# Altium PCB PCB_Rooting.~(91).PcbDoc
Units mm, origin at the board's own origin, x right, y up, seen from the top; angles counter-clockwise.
Board outline 68.5 x 51 mm, 4 copper layers (Top Layer, Mid-Layer 1, Mid-Layer 2, Bottom Layer); 59 components, 42 nets, 197 pads, 55 vias.
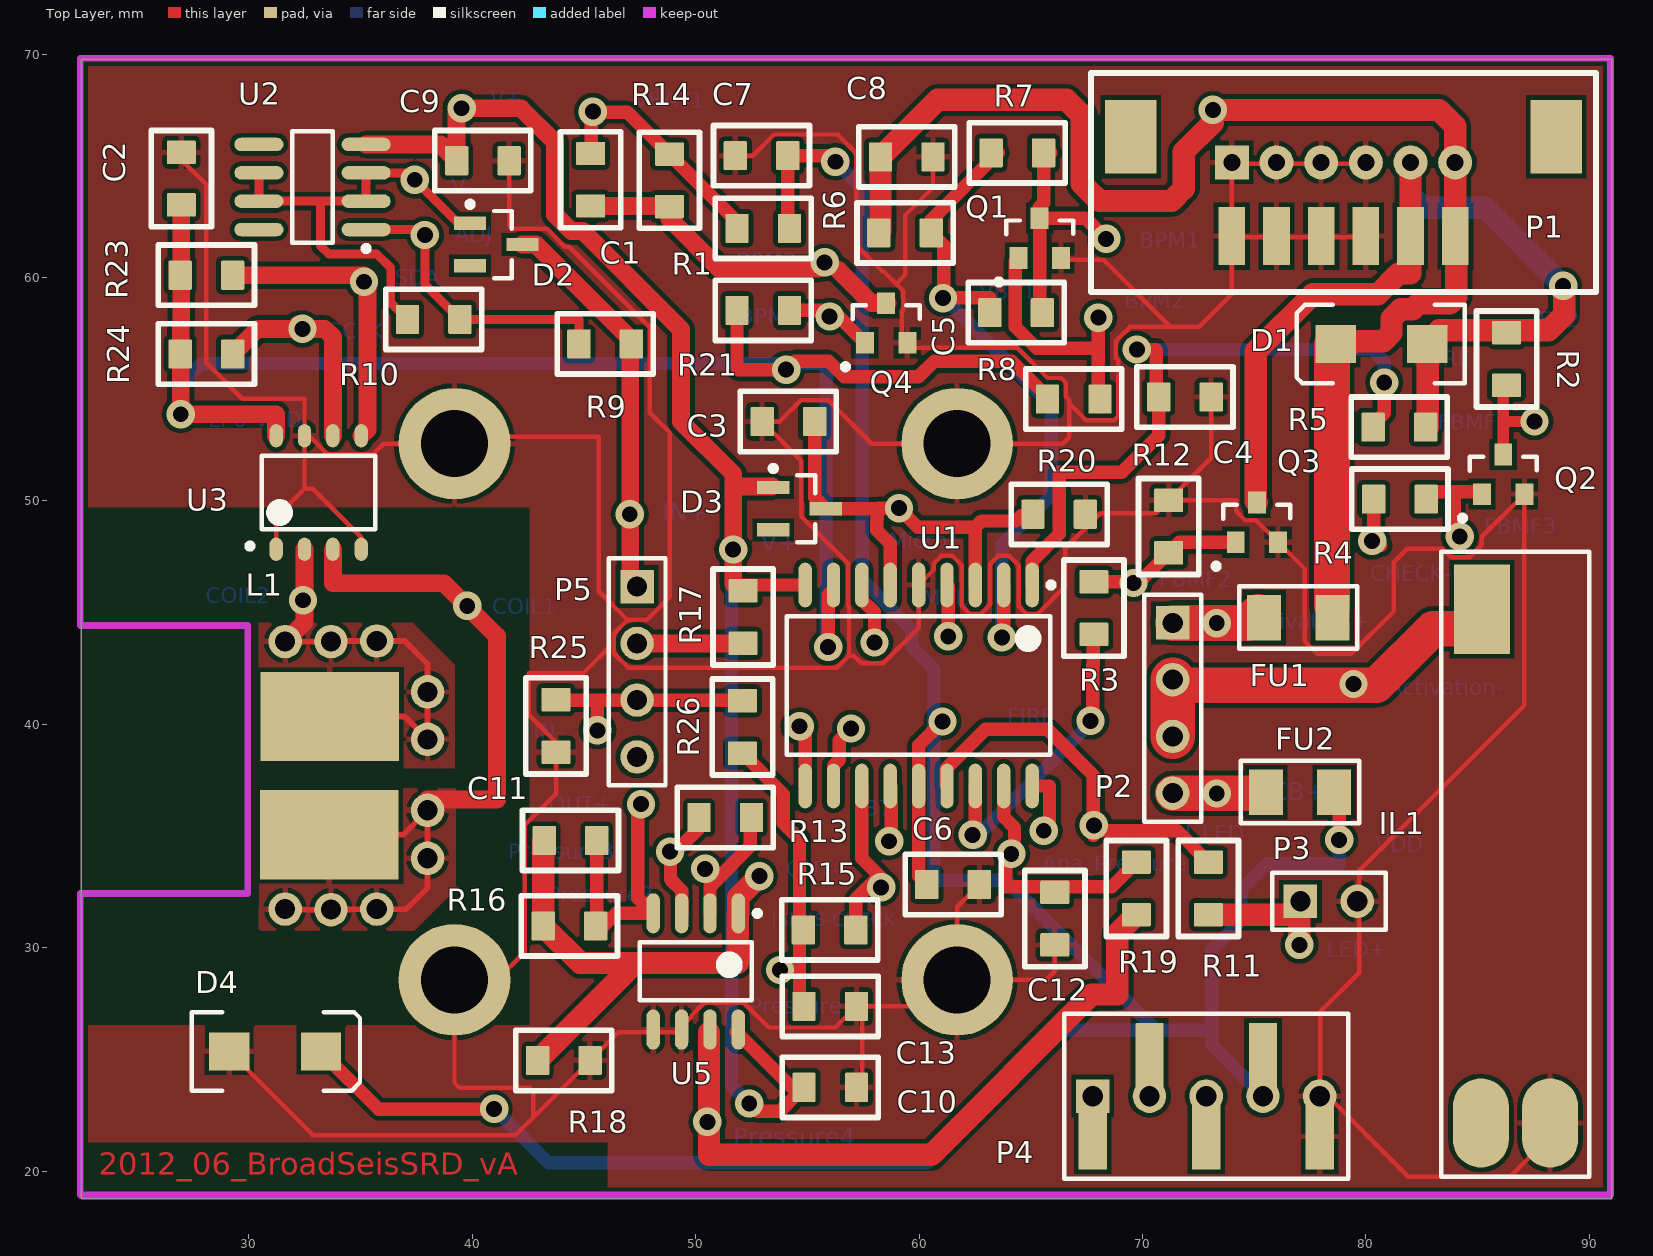
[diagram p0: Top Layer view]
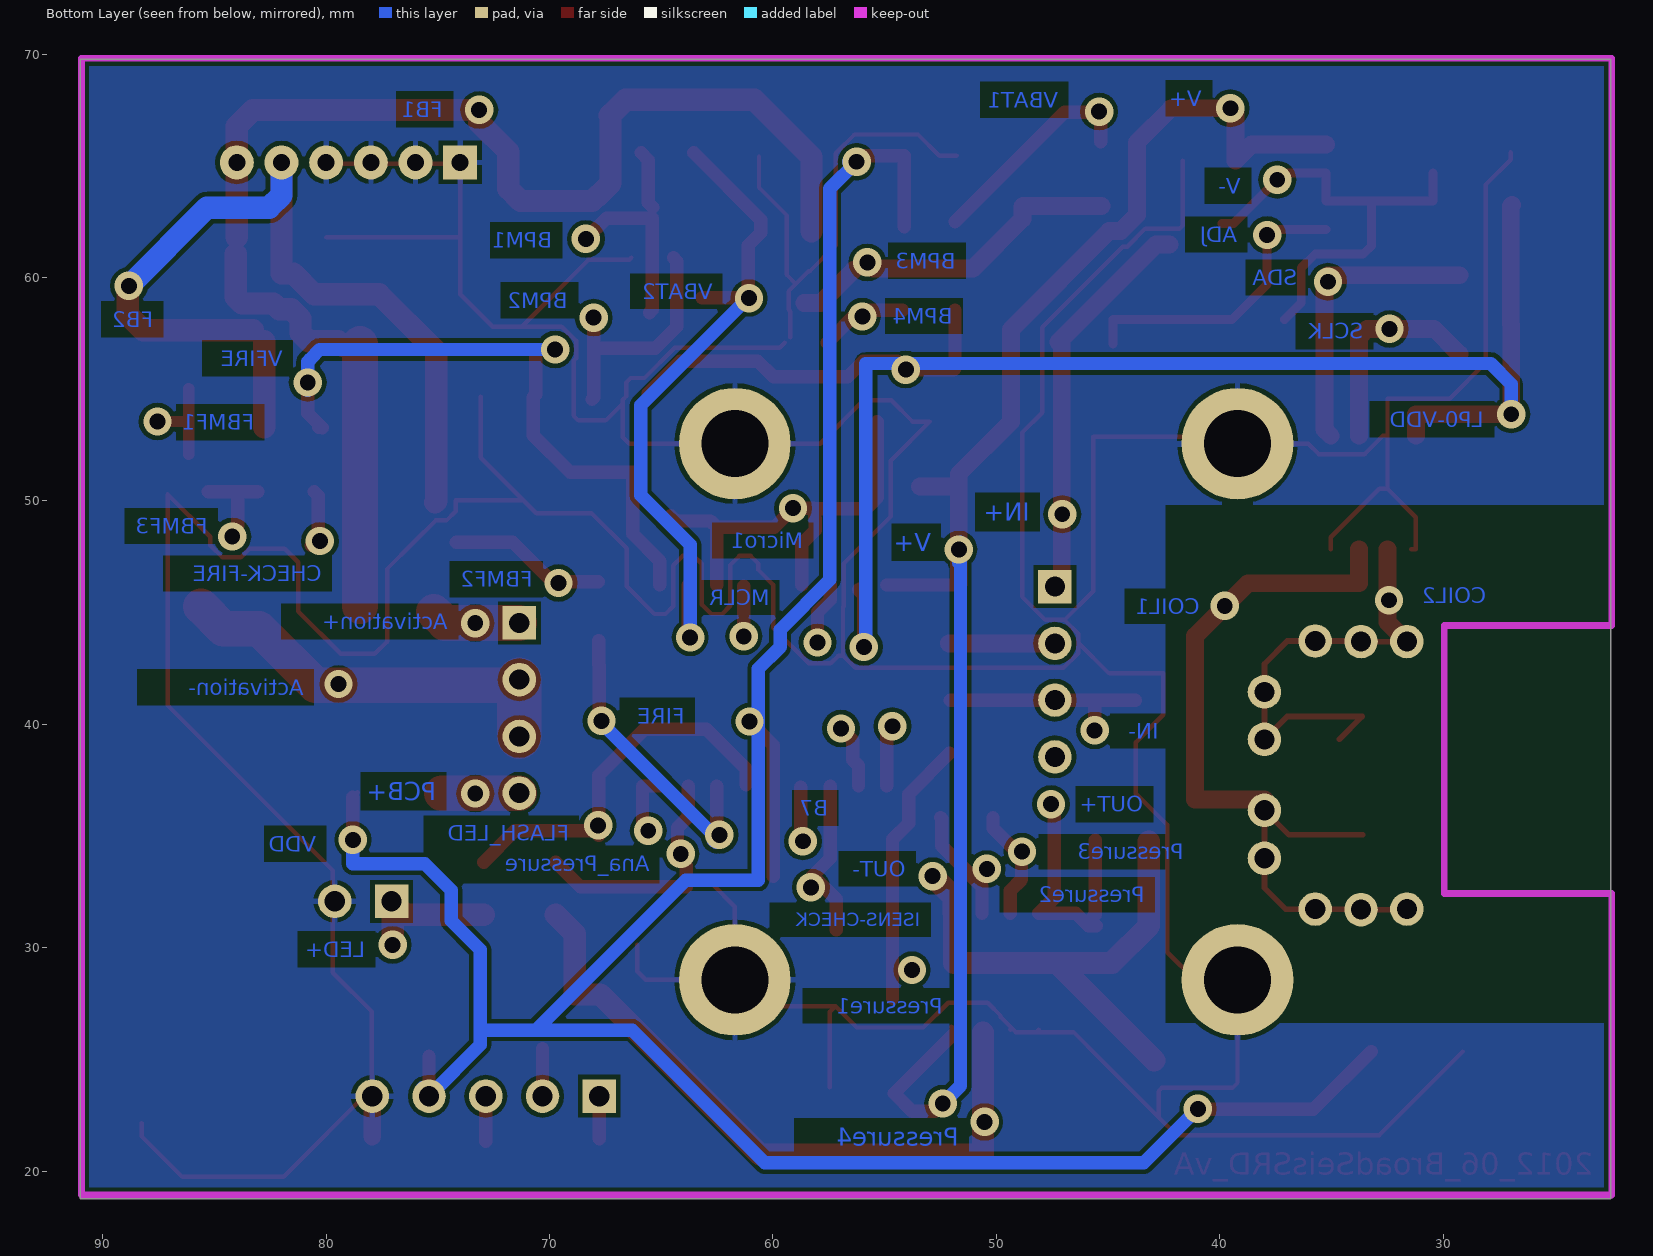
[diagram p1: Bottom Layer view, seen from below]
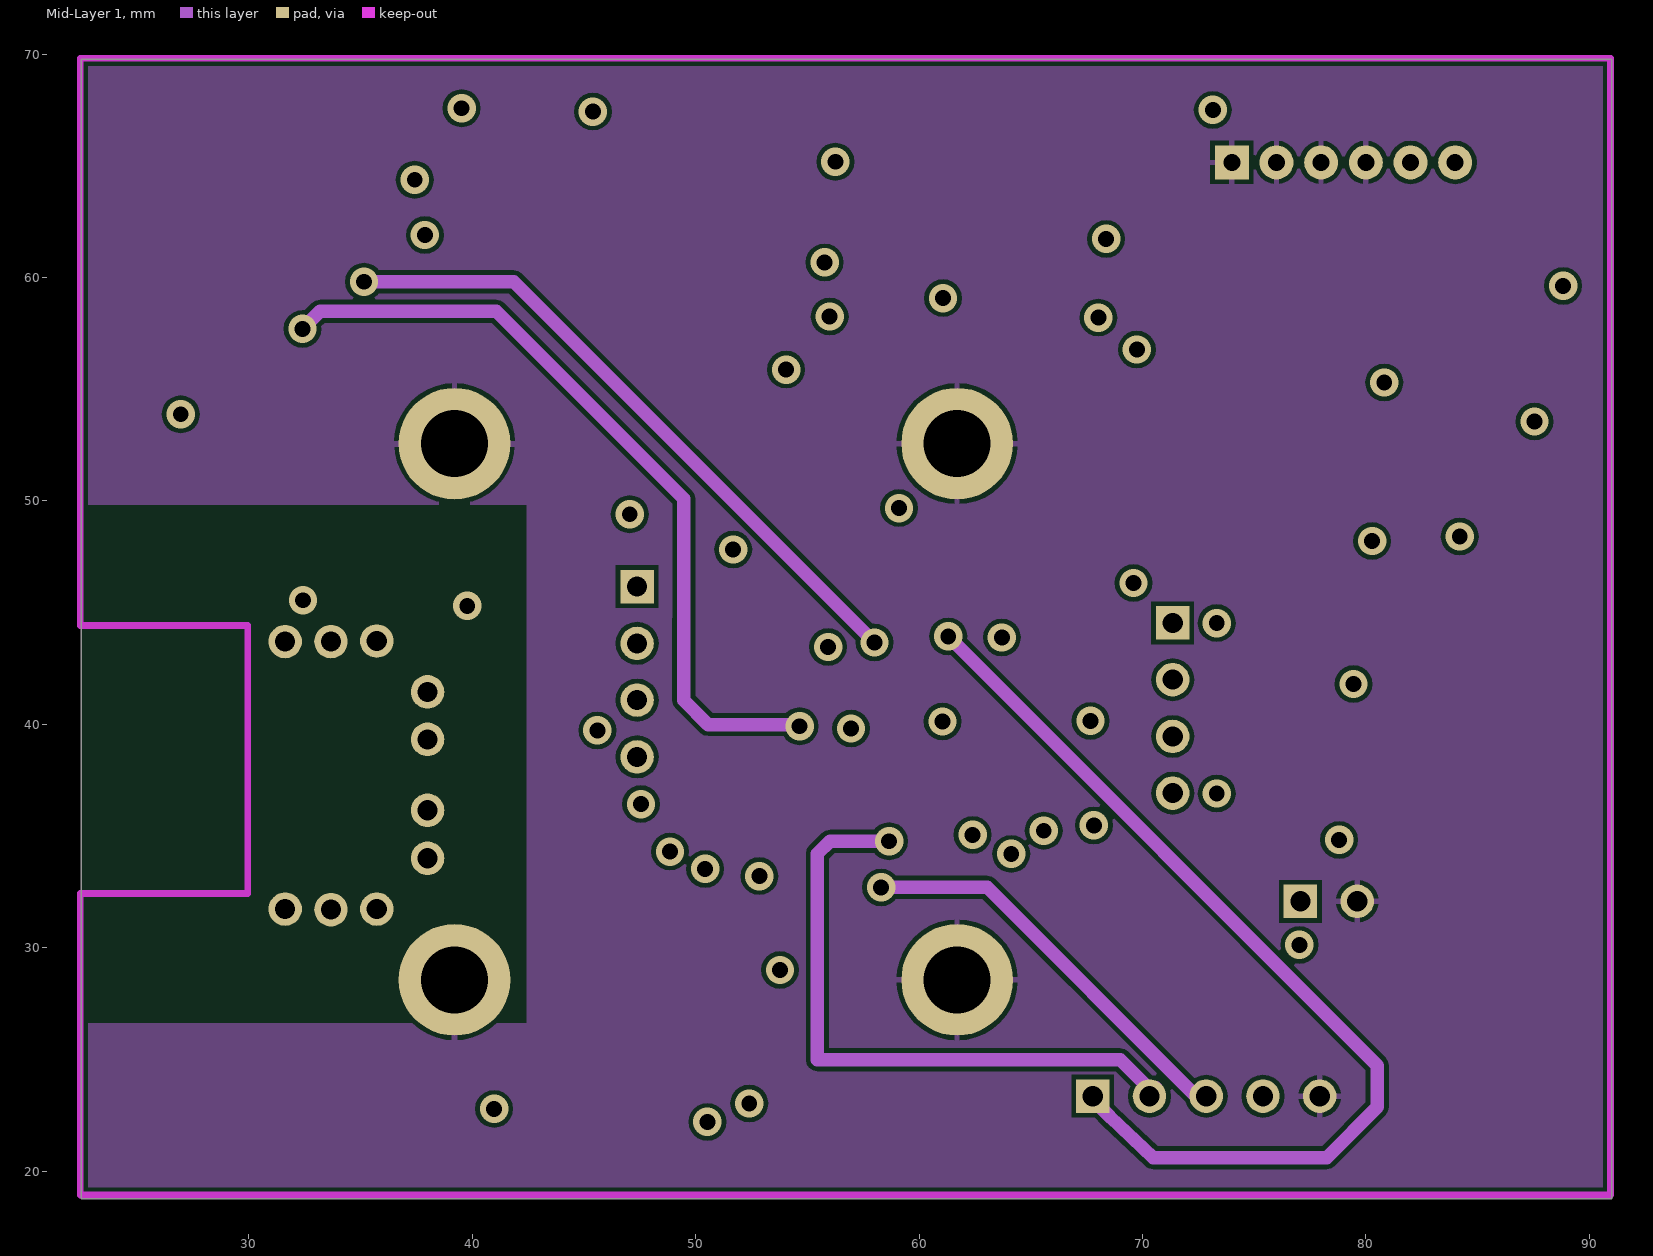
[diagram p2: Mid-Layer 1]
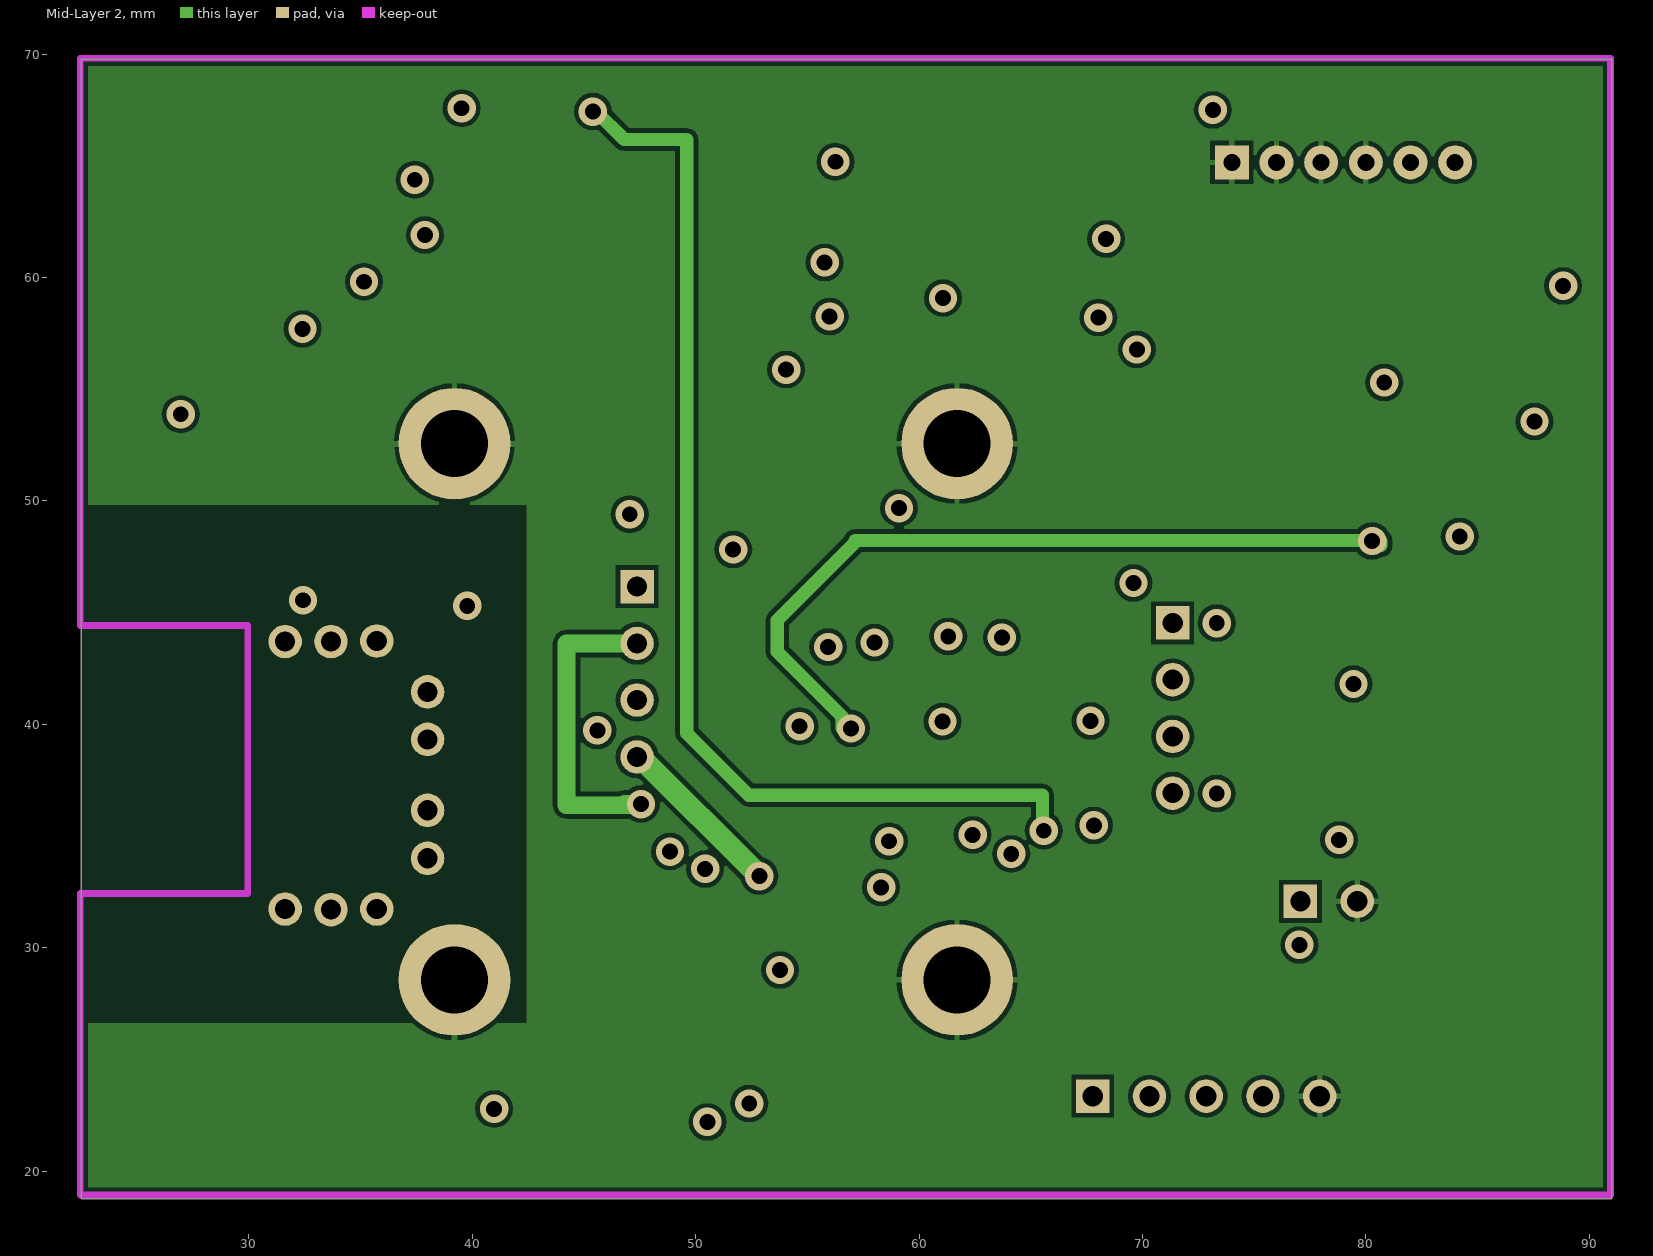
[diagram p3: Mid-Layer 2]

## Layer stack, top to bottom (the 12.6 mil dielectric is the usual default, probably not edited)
Top Layer: signal copper 0.0356
Dielectric: dielectric 0.32, FR-4, Dk 4.8
Mid-Layer 1: signal copper 0.0356
Dielectric: dielectric 0.32, FR-4, Dk 4.8
Mid-Layer 2: signal copper 0.0356
Dielectric: dielectric 0.32, FR-4, Dk 4.8
Bottom Layer: signal copper 0.0356

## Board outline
22.505,18.76 91.005,18.76 91.005,69.76 22.505,69.76

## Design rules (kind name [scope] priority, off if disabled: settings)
Clearance [All] p1: gap=0.2
HoleSize [All] p1: absolutevalues=TRUE maxlimit=5 minlimit=0.025 maxpercent=80.000 minpercent=20.000
PolygonConnect [All] p1: connectstyle=Relief reliefconductorwidth=0.254 reliefentries=4 polygonreliefangle="90 Angle"
RoomDefinition PCB_Schematics [InComponentClass('PCB_Schematics')] p1: confinementstyle=ConfineIn formatcopy=TRUE lockcomponents=FALSE outline 0,0 106.55,0 106.55,84.8 0,84.8
RoutingVias [All] p1: holewidth=0.6 width=1 viastyle="Through Hole" minholewidth=0.711 minwidth=1.27 maxholewidth=0.711 maxwidth=1.27
SilkscreenOverComponentPads [All] p1: minsilkscreentomaskgap=0.254
SolderMaskExpansion [All] p1: expansion=0.102
Width [All] p1: maxlimit=2 minlimit=0.2 preferedwidth=0.6
26 further rules are at their usual default settings.

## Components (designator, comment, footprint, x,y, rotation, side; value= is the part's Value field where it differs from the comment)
C1 "" 1608[0603] 45.3,64.375 r90 top
C2 "" 1608[0603] 26.975,64.425 r270 top
C3 "" 1608[0603] 54.15,53.55 r0 top
C4 "" 1608[0603] 71.9,54.65 r180 top
C5 "" 1608[0603] 64.35,58.425 r180 top
C6 "" 1608[0603] 61.525,32.825 r180 top
C7 "" 1608[0603] 52.95,65.45 r0 top
C8 "" 1608[0603] 59.45,65.4 r180 top
C9 "" 1608[0603] 40.475,65.225 r180 top
C10 "" 1608[0603] 56.025,23.75 r180 top
C11 "" 1608[0603] 44.4,34.8 r0 top
C12 "" 1608[0603] 66.075,31.3 r90 top
C13 "" 1608[0603] 56.025,27.375 r180 top
D1 "" DiodeRS1D(recommendedfootprint) 80.7,57.025 r180 top
D2 "" SOT-23_M 41.075,61.475 r0 top
D3 "" SOT-23_M 54.65,49.65 r0 top
D4 "" DiodeRS1D(recommendedfootprint) 31.175,25.35 r0 top
FU1 "1A" FU(recommendedfootprint) 76.975,44.775 r0 top
FU2 "200mA" FU(recommendedfootprint) 77.055,36.96 r180 top
IL1 "ILS" ILS 88.15,45.15 r270 top
L1 "" INDC4532 33.625,37.7 r270 top
P1 "ConnectorToFB" "HIROSE DF3DZ 6P-2V" 79,63.15 r0 top
P2 "Battery Pack pigtail" HDR1X4 71.355,44.535 r270 top
P3 "Connector to LED" HDR1X2 77.075,32.075 r0 top
P4 "Connector to Prog." HDR1X5 67.775,23.35 r0 top
P5 "Pressure Transducer pigtail" HDR1X4 47.38,46.16 r270 top
Q1 "" transistor_SOT-23(recommendedfootprint) 65.4,61.85 r90 top
Q2 "" transistor_SOT-23(recommendedfootprint) 86.15,51.275 r90 top
Q3 "" transistor_SOT-23(recommendedfootprint) 75.125,49.125 r90 top
Q4 "" transistor_SOT-23(recommendedfootprint) 58.525,58.05 r90 top
R1 "" J1-0603 53.025,62.2 r0 top
R2 "" J1-0603 86.3,56.35 r90 top
R3 "" J1-0603 67.825,45.2 r90 top
R4 "" J1-0603 81.525,50.075 r0 top
R5 "" J1-0603 81.5,53.3 r0 top
R6 "" J1-0603 59.375,62 r180 top
R7 "" J1-0603 64.4,65.575 r180 top
R8 "" J1-0603 66.925,54.55 r0 top
R9 "" J1-0603 45.95,57.025 r0 top
R10 "" J1-0603 38.275,58.125 r180 top
R11 "" J1-0603 72.95,32.65 r90 top
R12 "" J1-0603 71.175,48.85 r270 top
R13 "" J1-0603 51.325,35.825 r0 top
R14 "" J1-0603 48.825,64.35 r90 top
R15 "" J1-0603 56,30.8 r180 top
R16 "" J1-0603 44.35,30.975 r0 top
R17 "" J1-0603 52.125,44.8 r90 top
R18 "" 1608[0603] 44.1,24.95 r180 top
R19 "" J1-0603 69.725,32.65 r90 top
R20 "" J1-0603 66.275,49.4 r180 top
R21 "" J1-0603 53.025,58.525 r0 top
R23 "" J1-0603 28.1,60.1 r0 top
R24 "" J1-0603 28.1,56.575 r180 top
R25 "" J1-0603 43.75,39.925 r90 top
R26 "" J1-0603 52.1,39.875 r90 top
U1 "PIC16LF1827-I/SO" SOIC-SO18_L 59.98,41.735 r270 top
U2 "LM334D" SO8_N 32.85,64.05 r180 top
U3 "M24LR64" SO8N_N 33.125,50.375 r90 top
U5 "AD620BR" R-8D_N 50.005,28.935 r270 top

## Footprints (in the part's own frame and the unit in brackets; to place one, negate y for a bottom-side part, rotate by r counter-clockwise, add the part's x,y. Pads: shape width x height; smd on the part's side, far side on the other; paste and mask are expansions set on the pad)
1608[0603] [mm] "Chip Capacitor, Body 1.6x0.8mm, IPC High Density"
  rrect10% 1.05x1.3 smd: 1(-1.175,0) 2(1.175,0)
  silkscreen extent -2.15,-1.35 2.15,1.35
DiodeRS1D(recommendedfootprint) [mm] "DO-214-AB/SMC; 2 C-Bend Leads; Body 7.9 x 5.9 mm, inc. leads (LxW)"
  rect 1.8x1.7 smd: 1(-2.05,0) 2(2.05,0)
  silkscreen extent -3.73,-1.75 3.8,1.75
FU(recommendedfootprint) [mm] "Thru-Hole; 2 Leads"
  rect 1.52x2.03 smd: 1(-1.525,0) 2(1.525,0)
  silkscreen extent -2.65,-1.4 2.65,1.4
HDR1X2 [mm] "Connector; Header; 2 Position"
  rect 1.5x1.5 hole 0.9: 1(0,0)
  round 1.5 hole 0.9: 2(2.54,0)
  silkscreen extent -1.27,-1.27 3.81,1.27
HDR1X4 [mm] "Connector; Header; 4 Position"
  rect 1.5x1.5 hole 0.9: 1(0,0)
  round 1.5 hole 0.9: 2(2.54,0) 3(5.08,0) 4(7.62,0)
  silkscreen extent -1.27,-1.27 8.89,1.27
HDR1X5 [mm] "Connector; Header; 5 Position"
  rect 1.27x2.96 smd: 1(0,-1.8) 2(2.54,1.8) 3(5.08,-1.8) 4(7.62,1.8) 5(10.16,-1.8)
  rect 1.5x1.5 hole 0.9: 1(0,0)
  round 1.5 hole 0.9: 2(2.54,0) 3(5.08,0) 4(7.62,0) 5(10.16,0)
  silkscreen extent -1.27,-3.7 11.43,3.7
"HIROSE DF3DZ 6P-2V" [mm]
  rect 2.3x3.3 smd: 0(-9.52,3.15) 0(9.52,3.15)
  rect 1.2x2.6 smd: 1(-5,-1.3) 2(-3,-1.3) 3(-1,-1.3) 4(1,-1.3) 5(3,-1.3) 6(5,-1.3)
  rect 1.524x1.524 hole 0.762: 1(-5,2)
  round 1.524 hole 0.762: 2(-3,2) 3(-1,2) 4(1,2) 5(3,2) 6(5,2)
  silkscreen extent -11.3,-3.8 11.3,6
ILS [mm]
  rect 4x2.5 smd: 1(0,-2.95)
  oval 4x2.5 smd: 2(23,-3) 3(23,0.1)
  silkscreen extent -2.58,-4.77 25.4,1.85
INDC4532 [mm] "Chip Inductor, Body 4.5x3.2mm, IPC High Density"
  round 1.5 hole 0.9: 1(-6.025,2.1) 1(-6,0.05) 1(-6,-2) 1(-3.75,4.375) 1(-1.625,4.375) 2(1.55,4.375) 2(3.7,4.375) 2(5.975,2.1) 2(5.975,-2) 2(6,0.05)
  rect 4x6.2 smd: 1(-2.65,0) 2(2.65,-0.025)
  Top Layer lines w0.254: -6,-2 -6,0.05 -6.025,0.075 -6.025,2.1 -6.025,3.35 -5,4.375 -3.75,4.375 -1.625,4.375 -2.65,3.35 -2.65,0 -1.625,1.025
J1-0603 [mm] "Chip Capacitor, Body 1.6x0.8mm, IPC High Density"
  rrect10% 1.05x1.3 smd: 1(-1.175,0) 2(1.175,0)
  silkscreen extent -2.15,-1.35 2.15,1.35
R-8D_N [mm] "SOIC, 8-Leads, Body 4.9x3.9mm, Pitch 1.27mm, IPC Medium Density"
  oval 1.8x0.6 smd: 1(-2.6,1.905) 2(-2.6,0.635) 3(-2.6,-0.635) 4(-2.6,-1.905) 5(2.6,-1.905) 6(2.6,-0.635) 7(2.6,0.635) 8(2.6,1.905)
  silkscreen extent -2.72,-2.5 1.3,2.88, body extent -2,-2.5 2,2.5, height 2.59
SO8_N [mm] "SOIC, 8-Leads, Body 4.9x3.9mm, Pitch 1.27mm, IPC Medium Density"
  oval 2.2x0.6 smd: 1(-2.4,1.905) 2(-2.4,-0.635) 2(-2.4,0.635) 2(2.4,-0.635) 2(2.4,0.635) 4(-2.4,-1.905) 5(2.4,-1.905) 8(2.4,1.905)
  silkscreen extent -2.53,-2.5 0.9,2.88, body extent -1.95,-2.45 1.95,2.45, height 1.75
SO8N_N [mm] "SOP, 8-Leads, Body 5.3x5.3mm, Pitch 1.27mm, IPC Medium Density"
  oval 1.04x0.6 smd: 1(-2.54,1.905) 2(-2.54,0.635) 3(-2.54,-0.635) 4(-2.54,-1.905) 5(2.54,-1.905) 6(2.54,-0.635) 7(2.54,0.635) 8(2.54,1.905)
  silkscreen extent -2.52,-2.54 1.65,3.2, body extent -2.29,-2.54 2.29,2.54, height 2.13
SOIC-SO18_L [mm] "SOIC, 18-Leads, Body 11.5x7.5mm, Pitch 1.27mm, IPC High Density"
  oval 2x0.6 smd: 1(-4.5,5.08) 2(-4.5,3.81) 3(-4.5,2.54) 4(-4.5,1.27) 5(-4.5,0) 6(-4.5,-1.27) 7(-4.5,-2.54) 8(-4.5,-3.81) 9(-4.5,-5.08) 10(4.5,-5.08) 11(4.5,-3.81) 12(4.5,-2.54) 13(4.5,-1.27) 14(4.5,0) 15(4.5,1.27) 16(4.5,2.54) 17(4.5,3.81) 18(4.5,5.08)
  silkscreen extent -4.62,-5.9 3.1,6.06, body extent -3.8,-5.95 3.8,5.95, height 2.65
SOT-23_M [mm] "SOT23, 3-Leads, Body 2.9x1.3mm, Pitch 0.95mm, Lead Span 2.5mm, IPC Low Density"
  rect 1.45x0.6 smd: 1(-1.175,0.95) 2(-1.175,-0.95) 3(1.175,0)
  silkscreen extent -1.3,-1.5 0.7,1.92, body extent -0.7,-1.5 0.7,1.5, height 1.1
transistor_SOT-23(recommendedfootprint) [mm] "SOT23, 3-Leads, Body 2.9x1.3mm, Pitch 0.95mm, Lead Span 2.5mm, IPC Low Density"
  rect 0.972x0.802 smd: 1(-0.975,0.95) 2(-0.975,-0.95) 3(0.8,0)
  silkscreen extent -2.17,-1.5 0.7,1.95, body extent -0.7,-1.5 0.7,1.5, height 1.1

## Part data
C1 C2 C3 C4 C5 C6 C7 C8 C9 C10 C11 C12 C13: library part "Cap Semi", "Capacitor (Semiconductor SIM Model)"
D1 D4: library part Diode, "Default Diode"
D2 D3: library part "Diode BAS16", "Silicon Switching Diode for High-Speed Switching"
FU1 FU2: library part "Fuse 1", "Fuse"
IL1: "SPDT Subminiature Toggle Switch, Right Angle Mounting, Vertical Actuation"
L1: library part Inductor, "Inductor"
P1: "Header, 6-Pin"
P2 P5: "Header, 4-Pin"
P3: "Header, 2-Pin"
P4: "Header, 5-Pin"
Q1 Q2 Q4: library part NPN, "NPN Bipolar Transistor"
Q3: library part MOSFET-IRLML, "N-Channel MOSFET"
R1 R2 R3 R4 R5 R6 R7 R8 R9 R10 R11 R12 R13 R14 R15 R16 R17 R18 R19 R20 R21 R23 R24 R25 R26: library part Res3, "Resistor"
U1: "EPROM-Based 8-Bit CMOS Microcontroller, 25 Bytes RAM, 4 MHz, 18-Pin SOIC, 3.0 to 5.5V Supply Range, Extended Temperature"
U2: "Three Terminal Adjustable Current Source"
U3: "32 Kbit Serial I²C Bus EEPROM"
U5: "Low-Cost, Low-Power Instrumentation Amplifier"

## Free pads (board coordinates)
  round 5 hole 3: 1(39.205,28.56) 1(39.205,52.56) 1(61.705,28.56) 1(61.705,52.56)

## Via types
v1: diameter 1.27, hole 0.711, Top Layer to Bottom Layer, 55 vias

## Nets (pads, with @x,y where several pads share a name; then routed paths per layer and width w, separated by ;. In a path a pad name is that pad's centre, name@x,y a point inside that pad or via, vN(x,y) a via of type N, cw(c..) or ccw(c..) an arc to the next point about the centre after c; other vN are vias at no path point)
ACTIVATION+: FU1.1 P2.1 | length 4
  Top Layer w1.6: P2.1 74.68,44.535 FU1.1@75.185,45.04
  other v1: 73.325,44.525
ACTIVATION-: IL1.1 P2.2 P2.3 | length 18.3
  Top Layer w0.2: P2.2 P2.2@71.6,41.75
  Top Layer w1.6: P2.2@71.6,41.75 80.475,41.75 83.005,44.28 84.605,44.28 IL1.1@85.6,45.275
  Top Layer w2: P2.3 P2.2
  other v1: 79.45,41.8
ADJ: R9.1 R10.1 U2.1 | length 13.6
  Top Layer w0.4: U2.1 37.635,62.145 v1(37.88,61.9) 37.88,59.695 R10.1 44.76,58.125 ; R9.1 44.775,58.11
ANA_PRESSURE: C12.2 R19.2 U1.17 | length 11.1
  Top Layer w0.2: v1@63.905,33.685 v1@64.273,34.052
  Top Layer w0.6: U1.17 63.79,35.858 64.273,35.375 v1@64.273,34.052 ; v1@63.88,33.66 63.88,32.72 68.62,32.72 R19.2
  other v1: 64.125,34.2
B7: P4.2 U1.13 | length 33
  Top Layer w0.2: U1.13 U1.13@58.755,37.19
  Top Layer w0.6: v1(58.659,34.764) 58.659,35.014 58.755,35.11 U1.13@58.755,37.19 ; P4.2@70.315,23.35 P4.2@70.315,25.475
  Mid-Layer 1 w0.6: v1(58.659,34.764) 56.014,34.764 55.45,34.2 55.45,24.985 69.012,24.985 70.262,23.735 P4.2@70.595,23.735
BPM1: C5.1 Q1.3 R7.1 | length 10.3
  Top Layer w0.6: 65.375,63.15 65.575,63.35 65.575,65.25 R7.1@65.9,65.575 ; C5.1 65.4,58.55 Q1.3 67.45,62.65 v1(68.375,61.725)
BPM2: Q1.1 R8.2 | length 11.4
  Top Layer w0.6: Q1.1 64.3,60.725 64.3,57.799 65.274,56.825 68.025,56.825 ; v1(68.025,58.2) v1@68.325,58.2 ; v1@68.025,58.4 68.025,54.625 R8.2
BPM3: C1.1 Q4.3 R14.1 | length 14.9
  Top Layer w0.8: C1.1 R14.1@48.8,63.2 ; R14.1 48.825,62.625 51.05,60.4 55.5,60.4 v1(55.775,60.675) ; 56.387,60.337 57.875,58.85 Q4.3@58.6,58.85
BPM4: Q4.1 R21.2 | length 4
  Top Layer w0.6: R21.2 56.125,58.525 Q4.1
  other v1: 56,58.25
CHECK-FIRE: R4.1 U1.11 | length 40
  Top Layer w0.6: U1.11 56.17,38.145 56.425,38.4 56.425,39.28 v1(56.955,39.81) ; v1@80.35,48.4 80.35,50.225 R4.1@80.525,50.4 ; v1@80.675,48.001 v1@80.679,48.001
  Mid-Layer 2 w0.6: v1@56.565,39.81 56.565,40.335 53.65,43.25 53.65,44.65 57.15,48.15 57.15,48.225 v1@80.525,48.225 ; v1@80.434,48.048 80.524,48.048 80.679,48.202 80.679,48.001 80.675,48.001 v1@80.675,48.075
  other v1: 80.279,48.202
COIL1: L1.2 U3.3 | length 35.4
  Top Layer w0.254: L1.2@31.65,31.7 L1.2@33.675,31.7 ; L1.2@33.6,35.05 36.9,35.05 38,36.15 38,34 38,32.675 37.05,31.725 35.725,31.725 L1.2@33.7,31.725
  Top Layer w0.6: L1.2@31.625,31.725 L1.2@31.65,31.7 ; L1.2@33.675,31.7 L1.2@33.7,31.725
  Top Layer w0.8: U3.3 33.76,46.31 38.735,46.31 41.1,43.945 41.1,36.625 L1.2@38,36.625
  other v1: 39.775,45.3
COIL2: L1.1 U3.2 | length 4.5
  Top Layer w0.8: L1.1@31.625,43.7 32.49,44.565 U3.2
  other v1: 32.425,45.55
FB1: C8.2 D1.2 FU1.2 P1.6 R6.2 | length 61.8
  Top Layer w1: R6.2@58.275,62.075 C8.2 60.825,67.95 66.6,67.95 67.3,67.25 ; 67.275,64.225 67.275,67.3 ; 67.3,64.175 67.825,63.65 67.864,63.65 68.089,63.425 71.3,63.425 71.85,63.975 71.85,65.63 73.15,66.93 v1(73.15,67.5) 83.275,67.5 84,66.775 84,65.1 P1.6@84,61.8 ; D1.2@79.265,56.944 79.471,57.15 80.785,57.15 81.15,57.515 81.15,58.165 81.56,58.575 82.097,58.575 82.357,58.835 83.76,58.835 84.05,59.125 P1.6@84.05,61.05
  Top Layer w1.6: FU1.2@78.48,45.285 D1.2@78.48,57.025
FB2: D1.1 P1.5 Q3.3 R2.2 R5.2 | length 41.1
  Top Layer w1: Q3.3 75.075,49.975 75.075,56.7 77.625,59.25 80.538,59.25 81.463,60.175 82,60.175 P1.5@82,65.1 ; R5.2@82.775,53.3 D1.1@82.775,57.15 ; D1.1@83.275,57.635 88.185,57.635 88.875,58.325 v1@88.875,59.65
  Bottom Layer w1: P1.5@82,65.1 82,63.675 82.55,63.125 85.332,63.125 v1(88.832,59.625)
FBMF1: Q2.3 R2.1 | length 4.7
  Top Layer w0.2: Q2.3 Q2.3@86.3,52.225
  Top Layer w0.5: Q2.3 86.15,53.55 ; R2.1@86.15,55.025 86.15,53.55 ; v1@87.725,53.55 86.15,53.55
  other v1: 87.55,53.55
FBMF2: Q3.1 R3.2 R12.2 | length 7.1
  Top Layer w0.6: R3.2 69.875,46.375 R12.2 71.65,48.15 Q3.1
  other v1: 69.6,46.325
FBMF3: Q2.1 R4.2 | length 4.4
  Top Layer w0.6: R4.2@83.05,50.4 83.925,50.4 ; v1(84.204,48.402) 84.254,48.402 84.257,48.405 84.257,48.568 83.95,48.875 83.95,50.375 83.925,50.4 ; Q2.1@85.275,50.4 83.925,50.4
FIRE: R3.1 U1.16 | length 14.3
  Top Layer w0.6: v1(62.4,35.05) 62.49,35.05 62.58,34.96 62.58,34.86 62.655,34.785 62.605,34.785 62.52,34.87 U1.16 ; v1(67.675,40.15) 67.775,40.25 67.775,42.65 67.805,42.68 R3.1@67.805,43.75
  Bottom Layer w0.6: v1(62.4,35.05) 62.49,35.05 62.58,34.96 v1@67.775,40.155 ; v1@62.53,34.71 62.605,34.785 v1@62.655,34.785
FLASH_LED: R11.2 U1.15 | length 17.5
  Top Layer w0.2: U1.15@61.205,37.28 U1.15
  Top Layer w0.6: U1.15@61.205,37.28 61.205,38.005 62.975,39.775 65.75,39.775 67.805,37.72 v1@67.805,35.02 ; v1(67.825,35.475) 68.075,35.225 71.55,35.225 R11.2
GND: C2.1 C3.1 C4.1 C6.1 C7.1 C8.1 C9.1 C10.1 C12.1 C13.1 D4.1 IL1.3 P1.1 P1.2 P1.3 P1.4 P3.2 P4.5 pad.1 Q1.2 Q2.2 Q3.2 Q4.2 R12.1 R18.1 R20.1 R25.1 U1.5 U3.1 U3.4 U3.7 U5.5 U5.6 | length 372.2
  Top Layer w0.2: C2.1 26.975,65.275 28.1,64.15 28.1,56.181 29.706,54.575 32.49,54.575 U3.7 ; D4.1 32.865,21.61 41.935,21.61 42.725,22.4 ; U3.1@31.421,47.835 U3.1 31.22,49.27 32.49,50.54 ; U3.4 35.03,48.37 32.86,50.54 32.49,50.54 ; pad.1@38.08,54.26 39.48,52.86 45.665,52.86 45.665,45.95 46.945,44.67 ; pad.1@38.79,26.913 pad.1@38.79,27.87 ; pad.1@39.205,28.56 39.205,23.945 39.43,23.72 42.587,23.72 42.725,23.581 42.725,22.4 ; pad.1@39.205,52.56 36.035,52.56 35.57,52.095 33.511,52.095 32.691,52.915 U3.7 ; pad.1@39.48,28.56 pad.1@40.45,29.53 ; pad.1@41.11,28.56 42.35,29.8 42.35,35.494 43.75,36.894 R25.1 43.75,39.2 42.525,40.425 42.525,42.275 44.955,42.275 46.33,43.65 ; C9.1 41.65,62.324 41.799,62.175 43.342,62.175 44.142,61.375 44.344,61.375 47.95,57.769 47.95,53.95 48.85,53.05 48.85,45.706 47.814,44.67 46.945,44.67 ; U5.5 U5.5@48.215,26.22 ; U5.6 U5.6@49.305,26.4 ; C7.1 52.556,65.45 53.506,66.4 56.353,66.4 57.188,65.565 57.188,61.444 58.345,60.286 ; C10.1@57.45,23.75 57.45,27.125 C13.1 ; 58.4,60.286 58.975,59.711 ; Q4.2@59.226,57.324 59.226,58.486 59.3,58.56 59.3,59.386 58.975,59.711 ; Q4.2 59.7,56.85 64.4,56.85 65.75,55.5 66.369,55.5 66.575,55.294 66.575,54.675 66.725,54.525 66.725,52.85 66.435,52.56 pad.1@61.705,52.56 ; pad.1@60.52,27.375 C13.1 ; C8.1 60.625,64.025 59.375,62.775 59.375,60.111 58.975,59.711 ; pad.1@61.705,53.855 pad.1@61.705,52.56 ; C6.1 61.705,31.83 61.705,28.56 65.69,28.56 66.075,28.945 C12.1 ; Q1.2 66.435,60.79 68.26,60.79 71.25,57.8 ; 66.766,54.316 67.481,53.6 68.719,53.6 68.925,53.806 68.925,56.278 68.815,56.388 68.815,57.162 69.453,57.8 71.25,57.8 ; C4.1 73.075,51.925 R12.1 ; P1.4@80,61.8 P1.1@74,61.8 ; P1.4@80.498,65.1 74,65.1 74,61.85 P1.1@74,61.8 ; IL1.3 88.25,21.55 86.45,19.75 81.9,19.75 77.95,23.7 77.95,27.13 79.699,28.879 79.699,33.45 87.1,40.851 Q2.2 85.192,48.392 85.192,48.018 84.641,47.467 83.817,47.467 83.434,47.85 81.85,47.85 81.25,47.25 81.25,45.05 79.35,43.15 77.825,43.15 77.275,43.7 77.275,46.95 Q3.2 75.1,49.125 74.614,49.125 74.2,49.539 74.2,50.025 R12.1 ; 32.49,50.54 U3.7 ; 42.725,22.4 R18.1 46.545,26.22 U5.5@48.215,26.22 ; 46.33,43.65 46.33,44.055 46.945,44.67 ; 46.33,43.65 46.33,43.185 46.99,42.525 56.317,42.525 56.865,43.073 ; U5.5@48.215,26.22 49.125,26.22 U5.6@49.305,26.4 ; U5.6@49.305,26.4 49.796,26.891 49.796,26.939 50.391,27.535 52.159,27.535 53.269,26.425 56.25,26.425 C13.1 ; 56.865,43.073 57.07,43.073 57.418,42.725 58.392,42.725 59.98,44.313 U1.5 60.65,46.905 60.65,47.184 61.001,47.535 61.499,47.535 61.905,47.129 61.905,45.301 62.271,44.935 62.769,44.935 63.19,45.356 63.19,47.184 63.541,47.535 64.039,47.535 64.46,47.114 64.46,45.286 64.811,44.935 65.309,44.935 66.55,46.176 66.55,47.875 68.125,49.45 70.6,49.45 R12.1 ; 56.865,43.073 56.865,45.261 56.84,45.286 56.84,47.186 54.725,49.301 54.725,51.8 C3.1 53.756,53.55 54.706,54.5 55.944,54.5 57.884,52.56 pad.1@61.705,52.56 ; 71.25,57.8 72.549,57.8 74,59.251 P1.1@74,61.8
  Top Layer w0.8: P4.5@77.935,21.55 P4.5@77.935,23.35
IN+: D2.3 P5.1 R9.2 | length 18
  Top Layer w0.8: D2.3 42.85,61.475 R9.2@47.212,57.112 ; R9.2@47.075,57.25 47.075,46.465 P5.1
  other v1: 47.05,49.4
IN-: P5.3 R25.2 R26.2 | length 9.7
  Top Layer w0.6: R25.2@43.77,41.08 45.55,41.08 ; v1(45.6,39.725) 45.6,41.03 45.55,41.08 ; R26.2@52.07,41.08 P5.3 45.55,41.08
ISENS_CHECK: P4.3 R15.1 U1.12 | length 27.8
  Top Layer w0.6: R15.1 57.175,32.175 58.225,33.225 57.44,34.01 U1.12 ; P4.3@72.855,21.325 P4.3@72.855,23.35
  Mid-Layer 1 w0.6: v1(58.3,32.7) 63.05,32.7 72.4,23.35 72.523,23.35 P4.3@72.855,23.682
LED+: P3.1 R11.1 | length 6.3
  Top Layer w1: R11.1 76.475,31.475 P3.1@77.025,32.025 ; v1(77.025,30.125) P3.1@77.025,32.025 ; P3.1 P3.1@77.025,32.025
LP0-VDD: C2.2 R8.1 R21.1 R23.1 R24.2 U1.8 U3.8 | length 78.5
  Top Layer w0.2: U1.8@56.17,46.025 U1.8
  Top Layer w0.6: R21.1 51.85,55.925 51.9,55.875 v1(54.05,55.875) 54.425,56.25 55.95,56.25 56.65,55.55 59.975,55.55 60.675,56.25 64.152,56.25 65.175,55.227 65.175,55.225 R8.1@65.575,54.825 ; v1(55.93,43.46) 55.93,45.785 U1.8@56.17,46.025
  Top Layer w0.8: C2.2@26.925,63.25 26.975,63.2 26.975,57.925 ; 26.95,57.9 v1(26.95,53.875) 31.22,53.875 U3.8
  Bottom Layer w0.6: v1(26.95,53.875) 26.95,55.225 27.875,56.15 55.84,56.15 55.84,43.55 v1(55.93,43.46)
MCLR/: P4.1 U1.4 | length 50.3
  Top Layer w0.2: U1.4 U1.4@61.305,46.18
  Top Layer w0.6: v1(61.305,43.935) U1.4@61.305,46.18 ; P4.1@67.775,21.45 P4.1@67.775,23.35
  Mid-Layer 1 w0.6: v1(61.305,43.935) 80.515,24.725 80.515,22.865 78.25,20.6 70.475,20.6 68.545,22.43 67.335,23.64 68.055,23.02 P4.1@68.055,23.735
MICRO1: C3.2 D3.3 R20.2 U1.3 U1.6 | length 19.7
  Top Layer w0.6: C3.2 55.325,50.15 D3.3 58.14,49.65 ; 58.11,49.209 58.11,48.685 58.71,48.085 U1.6 ; 58.14,49.239 58.14,49.65 ; U1.3 62.52,48.825 ; R20.2@64.575,49.335 64.34,49.1 62.795,49.1 62.52,48.825 ; 58.14,49.65 58.165,49.675 v1(59.1,49.675) 59.95,48.825 62.52,48.825
OUT+: C11.2 P5.2 R16.2 R17.1 U5.4 | length 31.9
  Top Layer w0.6: R16.2 R16.2@45.89,30.975 ; C11.2 45.575,31.475 45.983,31.067 46.45,31.535 U5.4 47.413,32.222 47.413,36.264 v1@47.514,36.365 ; v1@47.45,36.429 47.502,36.377 v1@47.514,36.365 ; v1@47.552,36.327 v1@47.514,36.365 ; v1@47.575,36.427 v1@47.514,36.365
  Top Layer w0.8: P5.2 52.12,43.62 R17.1
  Mid-Layer 2 w0.8: P5.2 44.225,43.62 44.225,36.377 v1@47.502,36.377 ; v1@47.552,36.327 v1@47.502,36.377 ; v1(47.552,36.427) v1@47.452,36.427 ; v1@47.452,36.427 v1@47.502,36.377 ; v1@47.452,36.427 46.812,36.427 46.812,36.429 47.45,36.429 v1@47.452,36.427
OUT-: C11.1 P5.4 R16.1 R18.2 U5.1 | length 31.3
  Top Layer w1: R18.2 47.285,29.31 ; C11.1@43.175,34.75 R16.1 44.84,29.31 47.285,29.31 ; U5.1@51.88,31.505 51.88,29.31 47.285,29.31 ; U5.1 51.91,32.26 v1(52.85,33.2)
  Mid-Layer 2 w1: P5.4 47.51,38.54 v1(52.85,33.2)
PCB+: FU2.2 P2.4 | length 3.5
  Top Layer w1.6: P2.4 FU2.2@74.825,36.915
  other v1: 73.325,36.9
PRESSURE1: C13.2 R15.2 R26.1 | length 12.9
  Top Layer w0.6: R26.1 53.925,36.875 53.925,35.575 54.65,34.85 54.65,28.95 ; v1(53.775,29) 54.6,29 54.65,28.95 ; C13.2@54.65,27.725 54.65,28.95
PRESSURE2: R13.2 U5.2 | length 5.1
  Top Layer w0.6: U5.2 50.64,32.74 52.45,34.55 52.45,35.775 R13.2
  other v1: 50.425,33.525
PRESSURE3: R13.1 U5.3 | length 5
  Top Layer w0.6: U5.3 49.37,32.555 48.875,33.05 48.875,34.075 50.15,35.35 R13.1
  other v1: 48.85,34.3
PRESSURE4: R19.1 U5.7 | length 30.7
  Top Layer w1: U5.7@50.596,26.201 50.596,20.725 60.55,20.725 67.725,27.9 68.875,27.9 68.875,30.625 R19.1
  other v1: 50.525,22.2
SCLK: R24.1 U1.10 U3.6 | length 48.5
  Top Layer w0.6: v1(54.655,39.91) 54.9,39.665 U1.10
  Top Layer w0.8: R24.1 30.4,57.7 v1(32.4,57.7) ; v1@32.2,57.9 v1(32.4,57.7) ; U3.6 33.76,57.335 33.395,57.7 v1(32.4,57.7)
  Mid-Layer 1 w0.6: v1(32.4,57.7) 33.185,58.485 41.08,58.485 49.475,50.09 49.475,44.55 49.472,44.547 ; 49.472,44.753 49.472,44.547 ; v1@54.855,39.985 50.555,39.985 49.472,41.068 49.472,44.547
SDA: R23.2 U1.7 U3.5 | length 45.2
  Top Layer w0.6: U1.7 57.44,45.575 58.005,45.01 v1(58.005,43.66)
  Top Layer w0.8: R23.2 35.165,60.1 35.305,59.96 35.305,53.19 U3.5
  Mid-Layer 1 w0.6: v1(35.155,59.81) 41.855,59.81 v1@57.755,43.91
V+: C9.2 C10.2 D3.1 R17.2 U1.9 U2.4 U5.8 | length 73.6
  Top Layer w0.2: R17.2@51.68,46.285 R17.2@51.73,46.235 ; U5.8@51.812,26.238 U5.8 U5.8@52.025,26.45 ; v1(52.4,23.025) v1@52.75,22.675
  Top Layer w0.6: R17.2@51.73,46.235 U1.9 ; U5.8@51.812,26.238 54.575,23.475 53.775,22.675 v1@52.75,22.675
  Top Layer w0.8: U2.4 38.57,65.955 C9.2 v1@39.3,67.35 ; v1(39.525,67.575) 42.175,67.575 43.7,66.05 43.7,62.807 44.432,62.075 44.95,62.075 49.35,57.675 49.35,53.54 51.68,51.21 51.68,50.65 ; R17.2@51.68,46.285 v1(51.68,47.825) 51.68,50.65 ; D3.1@53.425,50.65 51.68,50.65
  Bottom Layer w0.6: v1(51.68,47.825) 51.68,47.23 51.65,47.2 51.65,48.115 51.605,48.16 51.605,23.82 v1(52.4,23.025)
V-: D2.1 R10.2 U2.2 | length 20.7
  Top Layer w0.4: U2.2@30.45,64.685 30.45,63.415 33.225,63.415 ; R10.2 36.35,58.875 36.35,60.425 35.725,61.05 33.575,61.05 33.2,61.425 33.2,63.39 33.225,63.415 ; v1@37.115,64.685 35.25,64.685 35.25,63.415 33.225,63.415 ; v1(37.425,64.375) 39.375,62.425 D2.1
VBAT1: C1.2 R1.1 R14.2 U1.18 | length 62.6
  Top Layer w0.6: 45.325,66.082 45.325,67.403 46.947,67.403 R14.2 R1.1@51.85,62.5 ; U1.18 65.84,37.235 65.84,35.495 v1(65.58,35.235)
  Mid-Layer 2 w0.6: v1@45.557,67.425 46.807,66.175 49.6,66.175 49.6,39.6 52.375,36.825 65.525,36.825 65.525,35.29 v1(65.58,35.235)
  other v1: 45.4,67.425
VBAT2: C5.2 R6.1 R7.2 U1.2 | length 30.5
  Top Layer w0.6: 63.175,59.1 61.1,59.1 61.1,61.45 R6.1 60.55,62.575 R7.2@63.55,65.575 ; v1(63.705,43.885) 63.79,43.97 U1.2
  Bottom Layer w0.6: v1@61.1,59.1 65.925,54.275 65.925,50.25 63.705,48.03 v1(63.705,43.885)
  other v1: 61.075,59.075
VDD: C6.2 C7.2 D4.2 FU2.1 P4.4 R1.2 U1.14 | length 125.2
  Top Layer w0.2: v1@40.955,22.76 v1(40.98,22.785) ; U1.14 U1.14@60.08,37.135 ; FU2.1 FU2.1@78.805,36.735
  Top Layer w0.6: D4.2 35.815,22.76 v1@40.955,22.76 ; R1.2@54.125,62.275 C7.2 v1@55.981,65.45 ; v1(56.253,65.178) v1@56.33,65.178 ; C6.2@59.98,33.195 U1.14 59.98,39.055 v1(61.05,40.125) ; P4.4@75.395,23.35 P4.4@75.395,25.15 ; v1(78.805,34.825) FU2.1@78.805,36.735
  Bottom Layer w0.6: v1(40.98,22.785) 43.394,20.371 60.366,20.371 66.305,26.31 70.625,26.31 ; v1@56.603,65.178 v1(56.253,65.178) 57.45,63.981 57.45,46.468 59.68,44.238 59.68,43.46 60.65,42.49 60.65,33.025 63.91,33.025 70.625,26.31 ; P4.4@75.395,23.35 P4.4@75.4,23.35 ; P4.4@75.675,23.735 75.343,23.402 73.1,25.645 73.1,26.31 ; v1(78.805,34.825) 78.805,33.76 75.585,33.76 74.4,32.575 74.4,31.2 73.1,29.9 73.1,26.31 ; 70.625,26.31 73.1,26.31
VFIRE: C4.2 R5.1 U1.1 | length 30.4
  Top Layer w0.6: U1.1 65.06,47.31 66.275,48.525 66.275,51.275 69.075,51.275 70.725,52.925 C4.2 70.625,54.75 70.625,56.75 70.6,56.775 v1(69.75,56.775) ; R5.1@80.175,53.275 R5.1@80.2,53.3 ; R5.1 R5.1@80.2,53.3 ; v1(80.825,55.3) 80.825,53.925 R5.1@80.2,53.3
  Bottom Layer w0.6: v1(69.75,56.775) 80.3,56.775 80.7,56.35 80.825,56.225 v1(80.825,55.3) v1@80.825,54.95
pads on no net: D2.2 D3.2 IL1.2 P1.0 U2.5 U2.8

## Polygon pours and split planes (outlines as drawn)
GND on Top Layer "Bottom Layer-No Net" (solid, pour order 8): 22.455,69.81 90.955,69.81 90.955,18.925 22.575,18.925 22.575,26.525 42.575,26.525 42.575,49.725 22.575,49.725
COIL1 on Top Layer "Top Layer-No Net" (solid, pour order 8): 30.45,30.8 30.5,30.75 37.1,30.75 37.4,30.75 39.35,32.7 39.25,32.8 39.25,37.125 30.525,37.125
COIL2 on Top Layer "Top Layer-No Net" (solid, pour order 11): 30.45,44.575 30.475,44.55 37.05,44.55 37.325,44.55 39.125,42.75 39.225,42.65 39.225,38.025 30.6,38.025 30.45,38.175
GND on Mid-Layer 1 "Bottom Layer-No Net" (solid, pour order 10): 22.455,69.81 90.955,69.81 90.955,18.925 22.455,18.925 22.45,18.93 22.45,26.625 42.45,26.625 42.45,49.825 22.45,49.825
GND on Mid-Layer 2 "Bottom Layer-No Net" (solid, pour order 12): 22.455,69.81 90.955,69.81 90.955,18.925 22.455,18.925 22.455,26.62 22.45,26.625 42.45,26.625 42.45,49.825 22.45,49.825
GND on Bottom Layer "Bottom Layer-No Net" (solid, pour order 14): 22.455,69.81 90.955,69.81 90.955,18.925 22.455,18.925 22.45,18.93 22.45,26.625 42.45,26.625 42.45,49.825 22.45,49.825

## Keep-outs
Keep-Out Layer:
  lines w0.3: 22.455,18.925 90.955,18.925 90.955,69.81 22.455,69.81 22.455,60.36 22.455,52.422 22.455,51.397 22.455,44.425 29.955,44.425 29.955,39.66 29.955,32.425 22.455,32.425 22.455,18.925

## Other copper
Top Layer:
  text "2012_06_BroadSeisSRD_vA" at 23.275,19.825 h1
Bottom Layer:
  text "V+" at 40.8,67.675 h0.7
  text "VBAT1" at 47.225,67.6 h0.7
  text "FB1" at 74.775,67.175 h0.7
  text "V-" at 39.05,63.75 h0.7
  text "ADJ" at 39.225,61.575 h0.7
  text "BPM1" at 69.875,61.325 h0.7
  text "BPM3" at 51.825,60.4 h0.7
  text "SDA" at 36.525,59.65 h0.7
  text "VBAT2" at 62.7,59.025 h0.7
  text "BPM2" at 69.175,58.625 h0.7
  text "BPM4" at 51.95,57.925 h0.7
  text "FB2" at 87.75,57.775 h0.7
  text "SCLK" at 33.575,57.25 h0.7
  text "VFIRE" at 81.95,56.025 h0.7
  text "LP0-VDD" at 28.175,53.3 h0.7
  text "FBMF1" at 83.225,53.175 h0.7
  text "IN+" at 48.5,49.1 h0.8
  text "FBMF3" at 85.3,48.525 h0.7
  text "Micro1" at 58.65,47.875 h0.7
  text "V+" at 52.925,47.75 h0.8
  text "CHECK-FIRE" at 80.2,46.4 h0.7
  text "FBMF2" at 70.75,46.15 h0.7
  text "COIL2" at 28.075,45.425 h0.7
  text "MCLR" at 60.15,45.325 h0.7
  text "COIL1" at 40.9,44.925 h0.7
  text "Activation+" at 74.55,44.25 h0.7
  text "Activation-" at 81,41.3 h0.7
  text "FIRE" at 63.95,40.025 h0.7
  text "IN-" at 42.725,39.35 h0.7
  text "PCB+" at 75.075,36.6 h0.8
  text "OUT+" at 43.425,36.075 h0.7
  text "B7" at 57.525,35.9 h0.7
  text "FLASH_LED" at 69.125,34.775 h0.7
  text "VDD" at 80.45,34.3 h0.7
  text "Pressure3" at 41.6,33.95 h0.7
  text "Ana_Pressure" at 65.525,33.425 h0.7
  text "OUT-" at 54.05,33.175 h0.7
  text "Pressure2" at 43.35,32.025 h0.7
  text "ISENS-CHECK" at 53.4,30.95 h0.6
  text "LED+" at 78.25,29.575 h0.7
  text "Pressure1" at 52.4,27.05 h0.7
  text "Pressure4" at 51.675,21.125 h0.8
